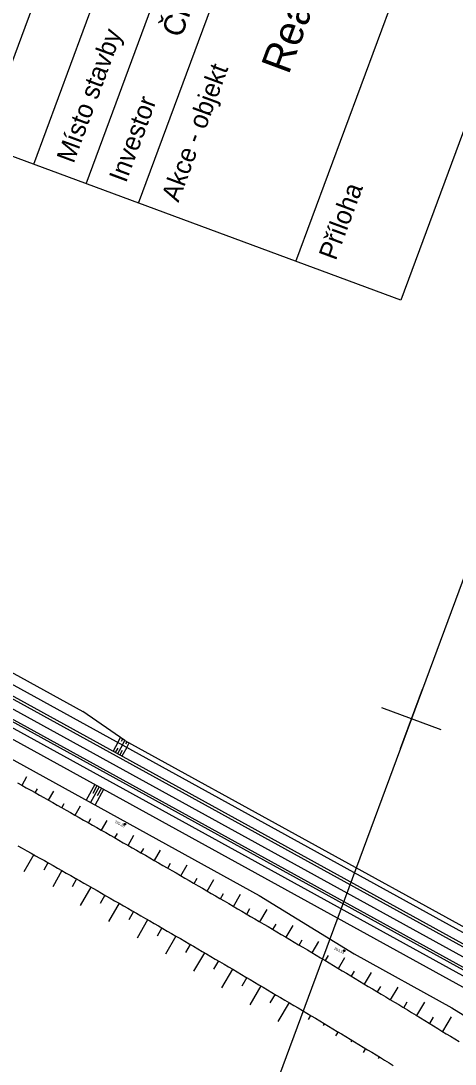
# Model space of a CAD drawing. Extents: x -552278 to -547230, y -1151007 to -1148251.
# Drawn here: x -550391.5 to -550305.8, y -1149028.3 to -1148822.2 of the extents above; entities that cross this region are included whole.
import ezdxf

# ---------------------------------------------------------------- set-up
doc = ezdxf.new("R2010")
doc.units = 0
for name, color, linetype in [('SO221815_VYSKOPIS', 7, 'Continuous'), ('u_trat navrh', 7, 'Continuous'), ('x_ram1', 7, 'Continuous'), ('x_rozpiska', 7, 'Continuous')]:
    doc.layers.add(name, color=color, linetype=linetype)

# ---------------------------------------------------------------- blocks, each defined once
blk = doc.blocks.new('SO221824_VYSKOPIS')
at = {"layer": 'SO221815_VYSKOPIS'}
for p, q in [((1.2, -0.9), (-1.2, 0.9)), ((0.9, 1.2), (-0.9, -1.2)), ((0.9, 1.2), (0, 0)), ((0, 0), (1.2, -0.9))]:
    blk.add_line(p, q, dxfattribs=at)
blk.add_lwpolyline([(-0.9, -1.2), (0, 0), (-1.2, 0.9)], dxfattribs=at)
blk.add_circle((0, 0), 1.5, dxfattribs=at)
for start, end in [(145.362, 235.1538), (325.362, 55.1538)]:
    blk.add_arc((0, 0), 1.5, start, end, dxfattribs=at)

msp = doc.modelspace()

# ---------------------------------------------------------------- linework, layer by layer
at = {"layer": 'u_trat navrh'}
for p, q in [((-550460.23, -1148921.16), (-550253.98, -1149034.78)), ((-550461.07, -1148922.69), (-550254.82, -1149036.32)), ((-550461.8, -1148924.01), (-550255.55, -1149037.63)), ((-550440.69, -1148924.79), (-550379.29, -1148958.62)), ((-550462.76, -1148925.76), (-550256.51, -1149039.38)), ((-550441.65, -1148926.54), (-550251.93, -1149031.06)), ((-550464.45, -1148928.82), (-550344.48, -1148994.92)), ((-550442.86, -1148928.73), (-550253.14, -1149033.25)), ((-550442.62, -1148928.29), (-550252.89, -1149032.81)), ((-550371.01, -1148964.32), (-550379.29, -1148958.62)), ((-550372.37, -1148964.71), (-550373.33, -1148966.46)), ((-550372.37, -1148964.71), (-550371.84, -1148963.75)), ((-550371.68, -1148964.49), (-550371.42, -1148964.03)), ((-550371.49, -1148965.19), (-550371.01, -1148964.32)), ((-550371.01, -1148964.32), (-550251.45, -1149030.19)), ((-550370.81, -1148965), (-550370.57, -1148964.56)), ((-550370.62, -1148965.68), (-550370.13, -1148964.8)), ((-550372.41, -1148965.83), (-550372.9, -1148966.7)), ((-550371.49, -1148965.19), (-550372.46, -1148966.95)), ((-550371.54, -1148966.31), (-550372.02, -1148967.19)), ((-550370.62, -1148965.68), (-550371.58, -1148967.43)), ((-550391.31, -1148973.18), (-550390.34, -1148971.44)), ((-550376.95, -1148973.03), (-550378.64, -1148976.1)), ((-550388.69, -1148974.66), (-550388.24, -1148973.86)), ((-550386.07, -1148976.13), (-550385.06, -1148974.34)), ((-550376.08, -1148973.51), (-550377.77, -1148976.58)), ((-550376.51, -1148973.27), (-550377.36, -1148974.81)), ((-550375.2, -1148974), (-550376.89, -1148977.06)), ((-550375.64, -1148973.76), (-550376.48, -1148975.29)), ((-550383.45, -1148977.61), (-550382.99, -1148976.79)), ((-550380.83, -1148979.09), (-550379.79, -1148977.25)), ((-550378.21, -1148980.57), (-550377.74, -1148979.73)), ((-550375.6, -1148982.06), (-550374.51, -1148980.15)), ((-550372.99, -1148983.55), (-550372.49, -1148982.67)), ((-550370.37, -1148985.04), (-550369.24, -1148983.06)), ((-550389, -1148986.87), (-550390.92, -1148990.28)), ((-550367.76, -1148986.54), (-550367.24, -1148985.63)), ((-550365.16, -1148988.04), (-550363.96, -1148985.96)), ((-550386.18, -1148988.47), (-550387.02, -1148989.96)), ((-550362.55, -1148989.54), (-550362, -1148988.58)), ((-550359.95, -1148991.04), (-550358.69, -1148988.87)), ((-550383.42, -1148990.03), (-550385.25, -1148993.25)), ((-550380.55, -1148991.67), (-550381.43, -1148993.22)), ((-550357.34, -1148992.55), (-550356.76, -1148991.55)), ((-550377.74, -1148993.27), (-550379.82, -1148996.92)), ((-550354.74, -1148994.06), (-550353.41, -1148991.78)), ((-550374.93, -1148994.88), (-550375.87, -1148996.52)), ((-550352.14, -1148995.58), (-550351.53, -1148994.52)), ((-550349.55, -1148997.1), (-550348.14, -1148994.68)), ((-550344.48, -1148994.92), (-550325.74, -1149006.5)), ((-550372.15, -1148996.47), (-550374.22, -1149000.07)), ((-550346.95, -1148998.62), (-550346.3, -1148997.5)), ((-550344.36, -1149000.14), (-550342.93, -1148997.71)), ((-550369.31, -1148998.11), (-550370.25, -1148999.74)), ((-550366.51, -1148999.72), (-550368.6, -1149003.35)), ((-550363.7, -1149001.35), (-550364.64, -1149002.96)), ((-550341.77, -1149001.67), (-550341.14, -1149000.6)), ((-550339.18, -1149003.2), (-550337.8, -1149000.88)), ((-550360.91, -1149002.97), (-550362.98, -1149006.52)), ((-550336.59, -1149004.73), (-550335.98, -1149003.71)), ((-550334, -1149006.27), (-550332.68, -1149004.04)), ((-550358.11, -1149004.6), (-550359.05, -1149006.23)), ((-550355.31, -1149006.24), (-550357.44, -1149009.87)), ((-550352.52, -1149007.87), (-550353.48, -1149009.52)), ((-550331.42, -1149007.81), (-550330.83, -1149006.83)), ((-550328.84, -1149009.35), (-550327.56, -1149007.21)), ((-550325.74, -1149006.5), (-550306.47, -1149017.11)), ((-550349.72, -1149009.52), (-550351.9, -1149013.21)), ((-550326.26, -1149010.9), (-550325.67, -1149009.91)), ((-550323.68, -1149012.45), (-550322.31, -1149010.17)), ((-550346.93, -1149011.16), (-550347.92, -1149012.83)), ((-550344.15, -1149012.81), (-550346.35, -1149016.53)), ((-550321.1, -1149014), (-550320.46, -1149012.93)), ((-550318.53, -1149015.55), (-550317.03, -1149013.08)), ((-550341.36, -1149014.46), (-550342.35, -1149016.12)), ((-550338.58, -1149016.11), (-550340.79, -1149019.83)), ((-550315.95, -1149017.11), (-550315.25, -1149015.95)), ((-550313.38, -1149018.67), (-550311.75, -1149015.99)), ((-550306.47, -1149017.11), (-550282.62, -1149031.85)), ((-550334.35, -1149018.64), (-550334.82, -1149019.43)), ((-550331.63, -1149020.27), (-550331.84, -1149020.62)), ((-550310.81, -1149020.24), (-550310.05, -1149018.98)), ((-550308.25, -1149021.8), (-550306.49, -1149018.93)), ((-550328.92, -1149021.9), (-550329.39, -1149022.67)), ((-550326.21, -1149023.53), (-550326.42, -1149023.88)), ((-550323.5, -1149025.17), (-550323.97, -1149025.94)), ((-550320.8, -1149026.81), (-550321.01, -1149027.16))]:
    msp.add_line(p, q, dxfattribs=at)
for points in [[(-550255.07, -1149036.76), (-550461.31, -1148923.13)], [(-550392.22, -1148972.68), (-550391.35, -1148973.16), (-550390.48, -1148973.65), (-550389.6, -1148974.14), (-550388.73, -1148974.63), (-550387.86, -1148975.12), (-550386.98, -1148975.61), (-550386.11, -1148976.11), (-550385.24, -1148976.6), (-550384.37, -1148977.09), (-550383.49, -1148977.58), (-550382.62, -1148978.07), (-550381.75, -1148978.57), (-550380.88, -1148979.06), (-550380.01, -1148979.55), (-550379.14, -1148980.05), (-550378.27, -1148980.54), (-550377.4, -1148981.04), (-550376.52, -1148981.53), (-550375.65, -1148982.03), (-550374.78, -1148982.52), (-550373.91, -1148983.02), (-550373.04, -1148983.51), (-550372.18, -1148984.01), (-550371.31, -1148984.51), (-550370.44, -1148985), (-550369.57, -1148985.5), (-550368.7, -1148986), (-550367.83, -1148986.5), (-550366.96, -1148987), (-550366.09, -1148987.5), (-550365.23, -1148988), (-550364.36, -1148988.5), (-550363.49, -1148989), (-550362.62, -1148989.5), (-550361.76, -1148990), (-550360.89, -1148990.5), (-550360.02, -1148991), (-550359.16, -1148991.5), (-550358.29, -1148992), (-550357.42, -1148992.51), (-550356.56, -1148993.01), (-550355.69, -1148993.51), (-550354.83, -1148994.02), (-550353.96, -1148994.52), (-550353.1, -1148995.02), (-550352.23, -1148995.53), (-550351.37, -1148996.03), (-550350.5, -1148996.54), (-550349.64, -1148997.04), (-550348.77, -1148997.55), (-550347.91, -1148998.06), (-550347.05, -1148998.56), (-550346.18, -1148999.07), (-550345.32, -1148999.58), (-550344.46, -1149000.08), (-550343.59, -1149000.59), (-550342.73, -1149001.1), (-550341.87, -1149001.61), (-550341.01, -1149002.12), (-550340.14, -1149002.63), (-550339.28, -1149003.14), (-550338.42, -1149003.65), (-550337.56, -1149004.16), (-550336.7, -1149004.67), (-550335.84, -1149005.18), (-550334.97, -1149005.69), (-550334.11, -1149006.2), (-550333.25, -1149006.72), (-550332.39, -1149007.23), (-550331.53, -1149007.74), (-550330.67, -1149008.25), (-550329.81, -1149008.77), (-550328.95, -1149009.28), (-550328.09, -1149009.8), (-550327.24, -1149010.31), (-550326.38, -1149010.83), (-550325.52, -1149011.34), (-550324.66, -1149011.86), (-550323.8, -1149012.37), (-550322.94, -1149012.89), (-550322.09, -1149013.4), (-550321.23, -1149013.92), (-550320.37, -1149014.44), (-550319.51, -1149014.96), (-550318.66, -1149015.47), (-550317.8, -1149015.99), (-550316.94, -1149016.51), (-550316.09, -1149017.03), (-550315.23, -1149017.55), (-550314.38, -1149018.07), (-550313.52, -1149018.59), (-550312.66, -1149019.11), (-550311.81, -1149019.63), (-550310.95, -1149020.15), (-550310.1, -1149020.67), (-550309.24, -1149021.2), (-550308.39, -1149021.72), (-550307.54, -1149022.24), (-550306.68, -1149022.76), (-550305.83, -1149023.29), (-550304.97, -1149023.81)], [(-550392.12, -1148985.12), (-550391.25, -1148985.61), (-550390.38, -1148986.1), (-550389.51, -1148986.59), (-550388.64, -1148987.08), (-550387.77, -1148987.57), (-550386.9, -1148988.06), (-550386.03, -1148988.55), (-550385.16, -1148989.05), (-550384.29, -1148989.54), (-550383.42, -1148990.03), (-550382.56, -1148990.52), (-550381.69, -1148991.02), (-550380.82, -1148991.51), (-550379.95, -1148992.01), (-550379.08, -1148992.5), (-550378.22, -1148993), (-550377.35, -1148993.49), (-550376.48, -1148993.99), (-550375.62, -1148994.48), (-550374.75, -1148994.98), (-550373.88, -1148995.48), (-550373.02, -1148995.97), (-550372.15, -1148996.47), (-550371.28, -1148996.97), (-550370.42, -1148997.47), (-550369.55, -1148997.97), (-550368.69, -1148998.46), (-550367.82, -1148998.96), (-550366.96, -1148999.46), (-550366.09, -1148999.96), (-550365.23, -1149000.46), (-550364.37, -1149000.96), (-550363.5, -1149001.47), (-550362.64, -1149001.97), (-550361.77, -1149002.47), (-550360.91, -1149002.97), (-550360.05, -1149003.47), (-550359.18, -1149003.97), (-550358.32, -1149004.48), (-550357.46, -1149004.98), (-550356.6, -1149005.48), (-550355.73, -1149005.99), (-550354.87, -1149006.49), (-550354.01, -1149007), (-550353.15, -1149007.5), (-550352.29, -1149008.01), (-550351.43, -1149008.51), (-550350.57, -1149009.02), (-550349.7, -1149009.53), (-550348.84, -1149010.03), (-550347.98, -1149010.54), (-550347.12, -1149011.05), (-550346.26, -1149011.56), (-550345.4, -1149012.06), (-550344.54, -1149012.57), (-550343.68, -1149013.08), (-550342.83, -1149013.59), (-550341.97, -1149014.1), (-550341.11, -1149014.61), (-550340.25, -1149015.12), (-550339.39, -1149015.63), (-550338.53, -1149016.14), (-550337.67, -1149016.65), (-550336.82, -1149017.16), (-550335.96, -1149017.68), (-550335.1, -1149018.19), (-550334.25, -1149018.7), (-550333.39, -1149019.21), (-550332.53, -1149019.73), (-550331.68, -1149020.24), (-550330.82, -1149020.76), (-550329.96, -1149021.27), (-550329.11, -1149021.78), (-550328.25, -1149022.3), (-550327.4, -1149022.81), (-550326.54, -1149023.33), (-550325.69, -1149023.85), (-550324.83, -1149024.36), (-550323.98, -1149024.88), (-550323.12, -1149025.4), (-550322.27, -1149025.91), (-550321.41, -1149026.43), (-550320.56, -1149026.95), (-550319.71, -1149027.47), (-550318.85, -1149027.99), (-550318, -1149028.51)]]:
    msp.add_lwpolyline(points, dxfattribs=at)
at = {"layer": 'x_ram1'}
for p, q in [((-550316.6, -1148965.91), (-550312.25, -1148954.19)), ((-550308.56, -1148962.23), (-550320.28, -1148957.88))]:
    msp.add_line(p, q, dxfattribs=at)
msp.add_lwpolyline([(-550696.5, -1149991.01), (-550168.47, -1148566.23), (-551020.03, -1148250.64), (-551548.05, -1149675.43)], close=True, dxfattribs=at)
at = {"layer": 'x_rozpiska'}
for p, q in [((-550378.65, -1148854.35), (-550269.95, -1148561.04)), ((-550368.3, -1148858.19), (-550259.6, -1148564.88)), ((-550337.24, -1148869.7), (-550228.54, -1148576.39)), ((-550399.35, -1148846.68), (-550325.18, -1148646.54)), ((-550389, -1148850.51), (-550314.83, -1148650.37))]:
    msp.add_line(p, q, dxfattribs=at)
msp.add_lwpolyline([(-550420.06, -1148839), (-550311.36, -1148545.7), (-550207.84, -1148584.06), (-550316.54, -1148877.37)], close=True, dxfattribs=at)

# ---------------------------------------------------------------- block references
at = {"layer": 'u_trat navrh', "xscale": 0.1, "yscale": 0.09999999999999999, "rotation": -31.851985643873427}
for p in [(-550371.01, -1148980.85), (-550327.7, -1149005.85)]:
    msp.add_blockref('SO221824_VYSKOPIS', p, dxfattribs=at)

# ---------------------------------------------------------------- texts
at = {"layer": 'u_trat navrh'}
for s, p in [('203,28', (-550373.04, -1148980.56)), ('203,13', (-550329.73, -1149005.56))]:
    msp.add_text(s, height=0.5, rotation=333.2568, dxfattribs=at).set_placement(p)
at = {"layer": 'x_rozpiska'}
for s, height, p in [('Realizace opatření KoPÚ k.ú. Měrovice nad Hanou', 5.888, (-550338.69, -1148832.94)), ('ČR - Státní pozemkový úřad, Krajský pozemkový úřad pro OK', 4.232, (-550359.88, -1148825.69)), ('Mikulášková Milada', 4.232, (-550401.08, -1148841.55)), ('Místo stavby', 3.68, (-550381.14, -1148850.48)), ('Akce - objekt', 3.68, (-550360.43, -1148858.16)), ('Investor', 3.68, (-550370.79, -1148854.32)), ('Příloha', 3.68, (-550329.38, -1148869.66))]:
    msp.add_text(s, height=height, rotation=69.6654, dxfattribs=at).set_placement(p)

doc.saveas('drawing.dxf')
